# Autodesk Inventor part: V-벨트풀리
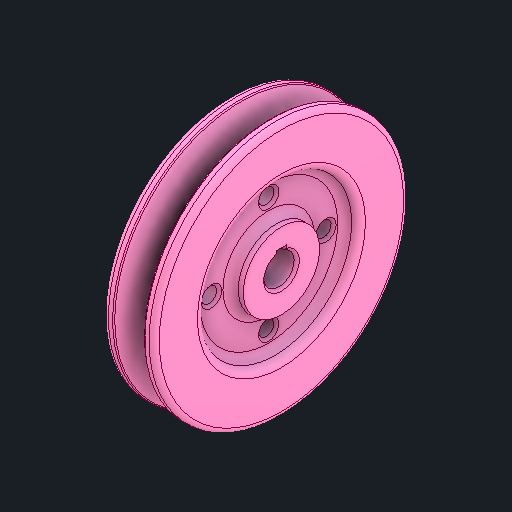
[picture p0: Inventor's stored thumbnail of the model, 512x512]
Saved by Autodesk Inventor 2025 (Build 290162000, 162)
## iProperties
Created: 2025-08
Part Number: V-벨트풀리
Material: 강철, 연강
Document SubType Name: Modeling
Designer: infra14
Density: 7.86 g/cm^3
Appearance: 기본값
Author: jhkim
Sending System: Autodesk Inventor 2026
Preprocessor: ST-DEVELOPER v20.1
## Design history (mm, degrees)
feature "솔리드1"
node "솔리드2"
